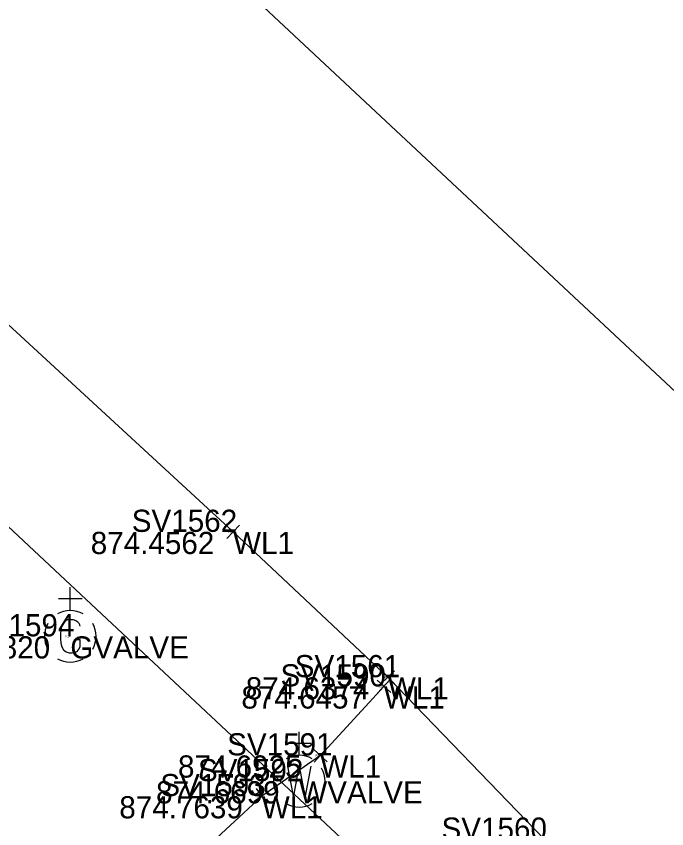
# Model space of a CAD drawing. Extents: x 1469677 to 1493262, y 375219 to 389293.
# Drawn here: x 1480149.29 to 1480184.52, y 379390.12 to 379434.1 of the extents above; entities that cross this region are included whole.
import ezdxf

# ---------------------------------------------------------------- set-up
doc = ezdxf.new("R2010")
doc.units = 0
for name, color, linetype in [('DR_X_Drive_Pipe', 7, 'Continuous'), ('DV_X_Text', 7, 'Continuous'), ('GK_Visualization', 7, 'Continuous'), ('PNTELEV', 7, 'Continuous'), ('PNTNO', 7, 'Continuous'), ('RW_P_Esmt_SW', 7, 'Continuous'), ('RW_X_Text', 7, 'Continuous'), ('SV_X_Mon_Cells_Found', 7, 'Continuous'), ('SV_X_Text_Elevation', 7, 'Continuous')]:
    doc.layers.add(name, color=color, linetype=linetype)

msp = doc.modelspace()

# ---------------------------------------------------------------- linework, layer by layer
at = {"layer": 'DR_X_Drive_Pipe'}
for points in [[(1480327.263, 379249.797), (1480312.798, 379263.799), (1480291.915, 379283.182), (1480274.385, 379298.987), (1480265.401, 379307.725), (1480264.495, 379308.458), (1480240.472, 379331.084), (1480234.677, 379335.863), (1480225.088, 379345.601), (1480208.322, 379361.342), (1480207.346, 379362.25), (1480199.528, 379369.768), (1480193.21, 379375.651), (1480182.823, 379385.139), (1480177.927, 379389.525), (1480169.423, 379398.321), (1480161.035, 379406.189), (1480144.924, 379421.019), (1480134.739, 379430.559), (1480121.485, 379441.998)], [(1480169.204, 379397.823), (1480165.761, 379394.087), (1480162.59, 379391.88), (1480159.156, 379388.706), (1480148.911, 379378.819), (1480120.344, 379350.087), (1480106.297, 379335.736), (1480080.736, 379308.289), (1480073.091, 379299.637), (1480056.748, 379281.628), (1480051.266, 379275.974)]]:
    msp.add_lwpolyline(points, dxfattribs=at)
at = {"layer": 'PNTELEV'}
for p, q in [((1480161.399, 379405.847), (1480160.67, 379406.531)), ((1480160.692, 379405.825), (1480161.377, 379406.554)), ((1480161.035, 379406.189), (1480161.035, 379406.189)), ((1480169.064, 379397.973), (1480169.783, 379398.668)), ((1480169.771, 379397.961), (1480169.076, 379398.68)), ((1480169.423, 379398.321), (1480169.423, 379398.321)), ((1480169.572, 379397.485), (1480168.836, 379398.162)), ((1480169.543, 379398.191), (1480168.865, 379397.456)), ((1480169.204, 379397.823), (1480169.204, 379397.823)), ((1480166.129, 379393.748), (1480165.393, 379394.425)), ((1480166.1, 379394.454), (1480165.422, 379393.719)), ((1480165.761, 379394.087), (1480165.761, 379394.087)), ((1480163, 379392.166), (1480162.18, 379391.594)), ((1480162.876, 379391.47), (1480162.304, 379392.29)), ((1480162.59, 379391.88), (1480162.59, 379391.88))]:
    msp.add_line(p, q, dxfattribs=at)
at = {"layer": 'PNTNO'}
for p, q in [((1480164.62, 379394.09), (1480164.62, 379395.362)), ((1480165.255, 379394.727), (1480163.983, 379394.727)), ((1480164.62, 379392.69), (1480164.62, 379392.69))]:
    msp.add_line(p, q, dxfattribs=at)
msp.add_lwpolyline([(1480163.983, 379393.51), (1480164.301, 379391.787), (1480164.62, 379393.51), (1480164.94, 379391.787), (1480165.256, 379393.51)], dxfattribs=at)
for start, end in [(60.0184, 120.0157), (150.0184, 209.9816), (330.0184, 29.9816), (239.9843, 299.9816)]:
    msp.add_arc((1480164.619, 379392.692), 1.4, start, end, dxfattribs=at)
at = {"layer": 'RW_X_Text'}
for p, q in [((1480152.218, 379401.934), (1480152.218, 379403.204)), ((1480152.855, 379402.569), (1480151.581, 379402.569)), ((1480152.218, 379400.534), (1480152.218, 379400.534))]:
    msp.add_line(p, q, dxfattribs=at)
msp.add_lwpolyline([(1480152.751, 379401.08), (1480152.736, 379401.151), (1480152.694, 379401.221), (1480152.623, 379401.292), (1480152.524, 379401.377), (1480152.453, 379401.406), (1480152.396, 379401.42), (1480152.311, 379401.434), (1480152.141, 379401.434), (1480152.07, 379401.42), (1480152.028, 379401.406), (1480151.971, 379401.377), (1480151.858, 379401.292), (1480151.787, 379401.193), (1480151.744, 379401.08), (1480151.716, 379400.924), (1480151.688, 379400.697), (1480151.688, 379400.399), (1480151.702, 379400.158), (1480151.759, 379399.974), (1480151.844, 379399.804), (1480151.914, 379399.747), (1480151.999, 379399.691), (1480152.155, 379399.634), (1480152.311, 379399.634), (1480152.467, 379399.662), (1480152.524, 379399.691), (1480152.581, 379399.719), (1480152.637, 379399.776), (1480152.694, 379399.861), (1480152.751, 379399.988), (1480152.751, 379400.343), (1480152.453, 379400.343)], dxfattribs=at)
for start, end in [(60.0184, 120.0157), (150.0184, 209.9816), (330.0184, 29.9816), (239.9843, 299.9816)]:
    msp.add_arc((1480152.218, 379400.534), 1.4, start, end, dxfattribs=at)
at = {"layer": 'SV_X_Mon_Cells_Found'}
msp.add_lwpolyline([(1477164.629, 382297.849), (1479615.888, 379904.59), (1480413.414, 379159.216)], dxfattribs=at)
at = {"layer": 'SV_X_Text_Elevation'}
msp.add_line((1479636.611, 379926.284), (1480557.828, 379065.308), dxfattribs=at)

# ---------------------------------------------------------------- texts
at = {"layer": 'DV_X_Text'}
for s, height, p in [('874.4562', 1.2, (1480153.325, 379404.989)), ('874.46', 0.06, (1480160.75, 379406.129)), ('874.4820', 1.2, (1480144.433, 379399.334)), ('874.48', 0.06, (1480151.936, 379400.474)), ('874.6374', 1.2, (1480161.723, 379397.121)), ('874.64', 0.06, (1480169.142, 379398.261)), ('874.6457', 1.2, (1480161.485, 379396.623)), ('874.65', 0.06, (1480168.922, 379397.763)), ('874.6925', 1.2, (1480158.051, 379392.887)), ('874.69', 0.06, (1480165.479, 379394.027)), ('874.6699', 1.2, (1480156.863, 379391.49)), ('874.67', 0.06, (1480164.338, 379392.63)), ('874.7639', 1.2, (1480154.871, 379390.68)), ('874.76', 0.06, (1480162.307, 379391.82))]:
    msp.add_text(s, height=height, dxfattribs=at).set_placement(p)
at = {"layer": 'GK_Visualization'}
for s, p in [('WL1', (1480161.035, 379404.989)), ('GVALVE', (1480152.218, 379399.334)), ('WL1', (1480169.423, 379397.121)), ('WL1', (1480169.204, 379396.623)), ('WL1', (1480165.761, 379392.887)), ('WVALVE', (1480164.62, 379391.49)), ('WL1', (1480162.59, 379390.68))]:
    msp.add_text(s, height=1.2, dxfattribs=at).set_placement(p)
at = {"layer": 'RW_P_Esmt_SW'}
for s, height, p in [('SV1562', 1.2, (1480155.546, 379406.189)), ('SV1562', 0.06, (1480160.761, 379406.189)), ('SV1594', 1.2, (1480146.729, 379400.534)), ('SV1594', 0.06, (1480151.944, 379400.534)), ('SV1561', 1.2, (1480164.376, 379398.321)), ('SV1590', 1.2, (1480163.602, 379397.823)), ('SV1561', 0.06, (1480169.171, 379398.321)), ('SV1590', 0.06, (1480168.924, 379397.823)), ('SV1591', 1.2, (1480160.714, 379394.087)), ('SV1591', 0.06, (1480165.509, 379394.087)), ('SV1592', 1.2, (1480159.131, 379392.69)), ('SV1593', 1.2, (1480157.092, 379391.88)), ('SV1592', 0.06, (1480164.346, 379392.69)), ('SV1593', 0.06, (1480162.315, 379391.88)), ('SV1560', 1.2, (1480172.325, 379389.525))]:
    msp.add_text(s, height=height, dxfattribs=at).set_placement(p)

doc.saveas('drawing.dxf')
